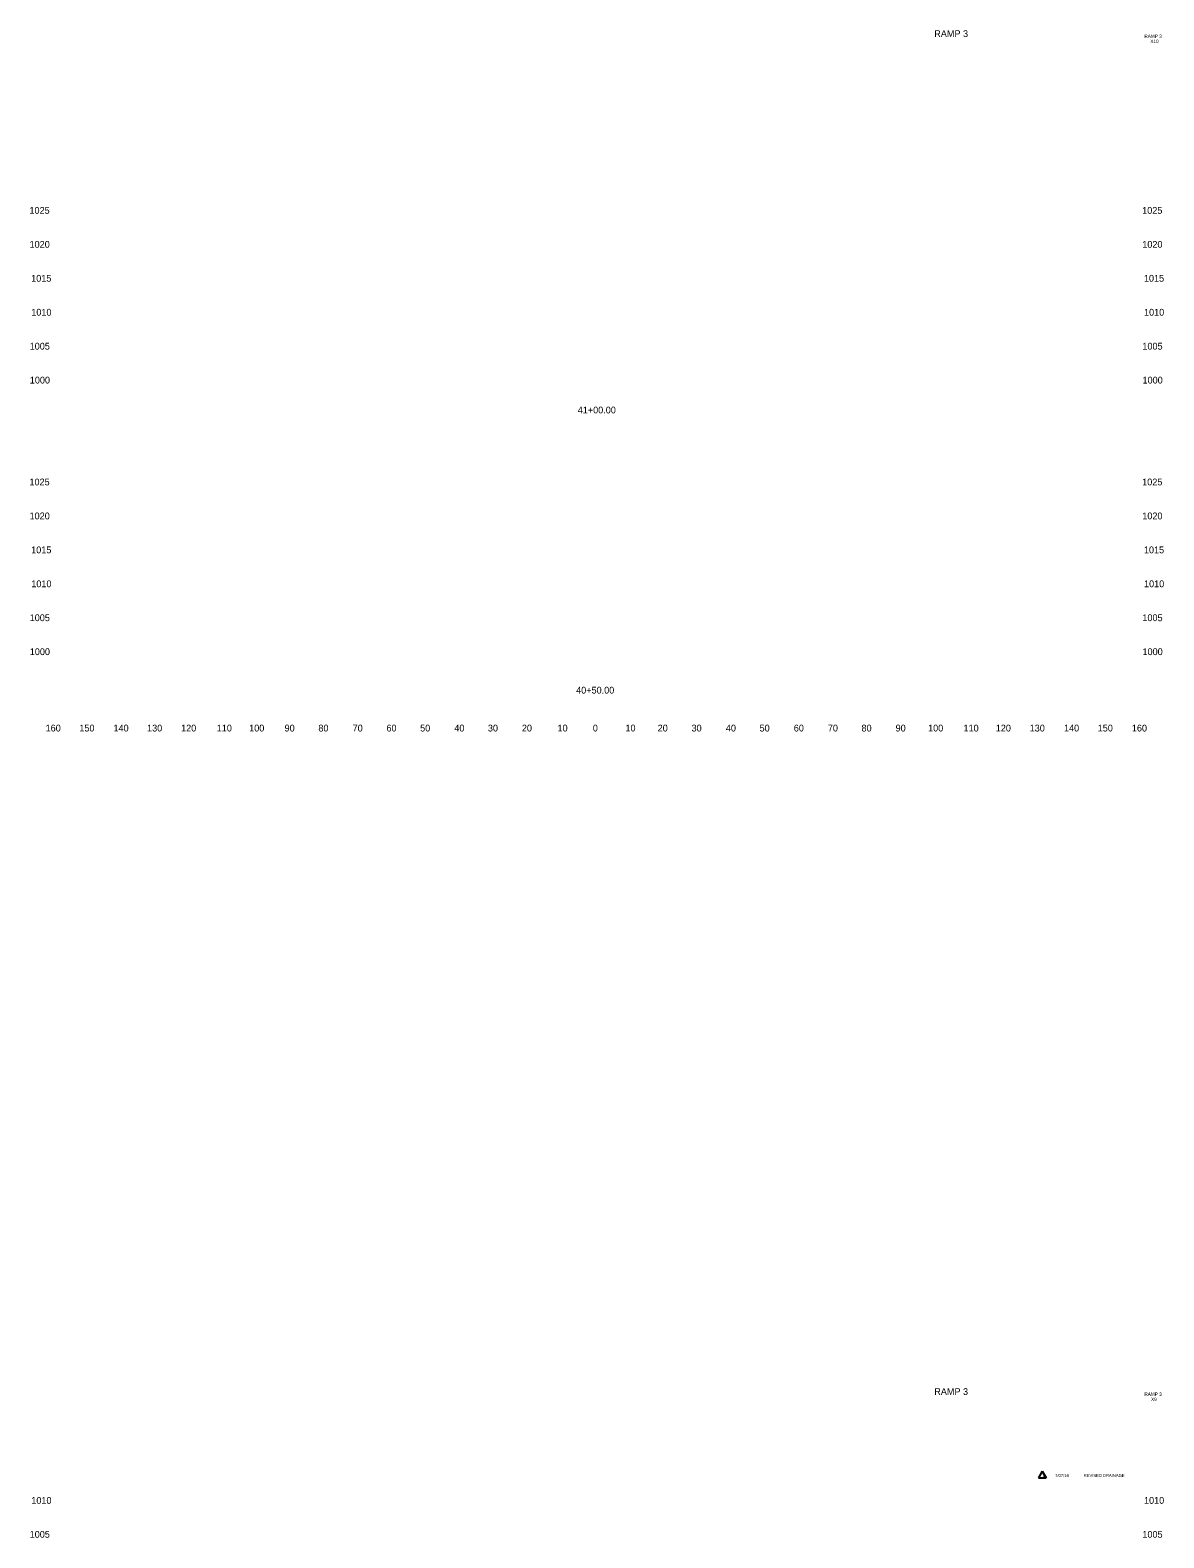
# Model space of a CAD drawing. Extents: x 4994 to 5843, y 4997 to 8804.
# Drawn here: x 4993.5 to 5327.5, y 8360 to 8804.1 of the extents above; entities that cross this region are included whole.
import ezdxf

# ---------------------------------------------------------------- set-up
doc = ezdxf.new("R2010")
doc.units = 0
for name, color, linetype in [('RD_SHT_ID', 7, 'Continuous'), ('RD_SHT_TX', 7, 'Continuous'), ('RD_XS_TX_Offset', 7, 'Continuous'), ('RD_XS_TX_Station', 7, 'Continuous')]:
    doc.layers.add(name, color=color, linetype=linetype)

msp = doc.modelspace()

# ---------------------------------------------------------------- linework, layer by layer
at = {"layer": 'RD_SHT_TX'}
for p, q in [((5291.7, 8379.64), (5290.56, 8377.61)), ((5290.56, 8377.61), (5292.84, 8377.61)), ((5291.7, 8379.64), (5292.84, 8377.61))]:
    msp.add_line(p, q, dxfattribs=at)

# ---------------------------------------------------------------- texts
at = {"layer": 'RD_SHT_ID'}
for s, height, p in [('RAMP 3', 2, (5259.89, 8802.06)), ('RAMP 3', 1, (5321.78, 8801.8)), ('X10', 1, (5323.53, 8800.3)), ('RAMP 3', 2, (5259.89, 8402.06)), ('RAMP 3', 1, (5321.78, 8401.8)), ('X9', 1, (5323.74, 8400.3))]:
    msp.add_text(s, height=height, dxfattribs=at).set_placement(p)
at = {"layer": 'RD_SHT_TX'}
for s, p in [('1', (5291.7, 8377.94)), ('7/07/16', (5295.48, 8377.9)), ('REVISED DRAINAGE', (5303.93, 8377.9))]:
    msp.add_text(s, height=0.88, dxfattribs=at).set_placement(p)
at = {"layer": 'RD_XS_TX_Offset'}
for s, p in [('1025', (4993.34, 8750)), ('1025', (5321.14, 8750)), ('1020', (4993.37, 8740)), ('1020', (5321.17, 8740)), ('1015', (4993.85, 8730)), ('1015', (5321.65, 8730)), ('1010', (4993.88, 8720)), ('1010', (5321.68, 8720)), ('1005', (4993.4, 8710)), ('1005', (5321.2, 8710)), ('1000', (4993.44, 8700)), ('1000', (5321.24, 8700)), ('1025', (4993.34, 8670)), ('1025', (5321.14, 8670)), ('1020', (4993.37, 8660)), ('1020', (5321.17, 8660)), ('1015', (4993.85, 8650)), ('1015', (5321.65, 8650)), ('1010', (4993.88, 8640)), ('1010', (5321.68, 8640)), ('1005', (4993.4, 8630)), ('1005', (5321.2, 8630)), ('1000', (4993.44, 8620)), ('1000', (5321.24, 8620)), ('160', (4998.1, 8597.5)), ('150', (5008.04, 8597.5)), ('140', (5018.1, 8597.5)), ('130', (5027.99, 8597.5)), ('120', (5038.01, 8597.5)), ('110', (5048.51, 8597.5)), ('100', (5058.07, 8597.5)), ('90', (5068.5, 8597.5)), ('80', (5078.46, 8597.5)), ('70', (5088.54, 8597.5)), ('60', (5098.5, 8597.5)), ('50', (5108.43, 8597.5)), ('40', (5118.5, 8597.5)), ('30', (5128.39, 8597.5)), ('20', (5138.4, 8597.5)), ('10', (5148.91, 8597.5)), ('0', (5159.3, 8597.5)), ('0', (5159.3, 8597.5)), ('10', (5168.91, 8597.5)), ('20', (5178.4, 8597.5)), ('30', (5188.39, 8597.5)), ('40', (5198.5, 8597.5)), ('50', (5208.43, 8597.5)), ('60', (5218.5, 8597.5)), ('70', (5228.54, 8597.5)), ('80', (5238.46, 8597.5)), ('90', (5248.5, 8597.5)), ('100', (5258.07, 8597.5)), ('110', (5268.51, 8597.5)), ('120', (5278.01, 8597.5)), ('130', (5287.99, 8597.5)), ('140', (5298.1, 8597.5)), ('150', (5308.04, 8597.5)), ('160', (5318.1, 8597.5)), ('1010', (4993.88, 8370)), ('1010', (5321.68, 8370)), ('1005', (4993.4, 8360)), ('1005', (5321.2, 8360))]:
    msp.add_text(s, height=2, dxfattribs=at).set_placement(p)
at = {"layer": 'RD_XS_TX_Station'}
for s, p in [('41+00.00', (5154.86, 8691.19)), ('40+50.00', (5154.39, 8608.67))]:
    msp.add_text(s, height=2, dxfattribs=at).set_placement(p)

doc.saveas('drawing.dxf')
